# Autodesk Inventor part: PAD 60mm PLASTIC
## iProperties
Created: 2007-03
Part Number: PAD 60mm PLASTIC
Document SubType Name: Modeling
Designer: Andy Moles
Material: ABS Plastic
Density: 1.06 g/cm^3
Author: Andy Moles
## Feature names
1. Revolution1
2. Extrusion1
3. Extrusion2
